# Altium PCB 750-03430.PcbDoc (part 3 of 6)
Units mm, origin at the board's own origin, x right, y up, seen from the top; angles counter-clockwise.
Board outline 141.61 x 63.5 mm, 6 copper layers (Top Layer, L2, L3, L4, L5, Bottom Layer), stack 1.557 mm thick; 401 components, 285 nets, 1356 pads, 1712 vias.
Unrouted connection lines stored in the file: 45.
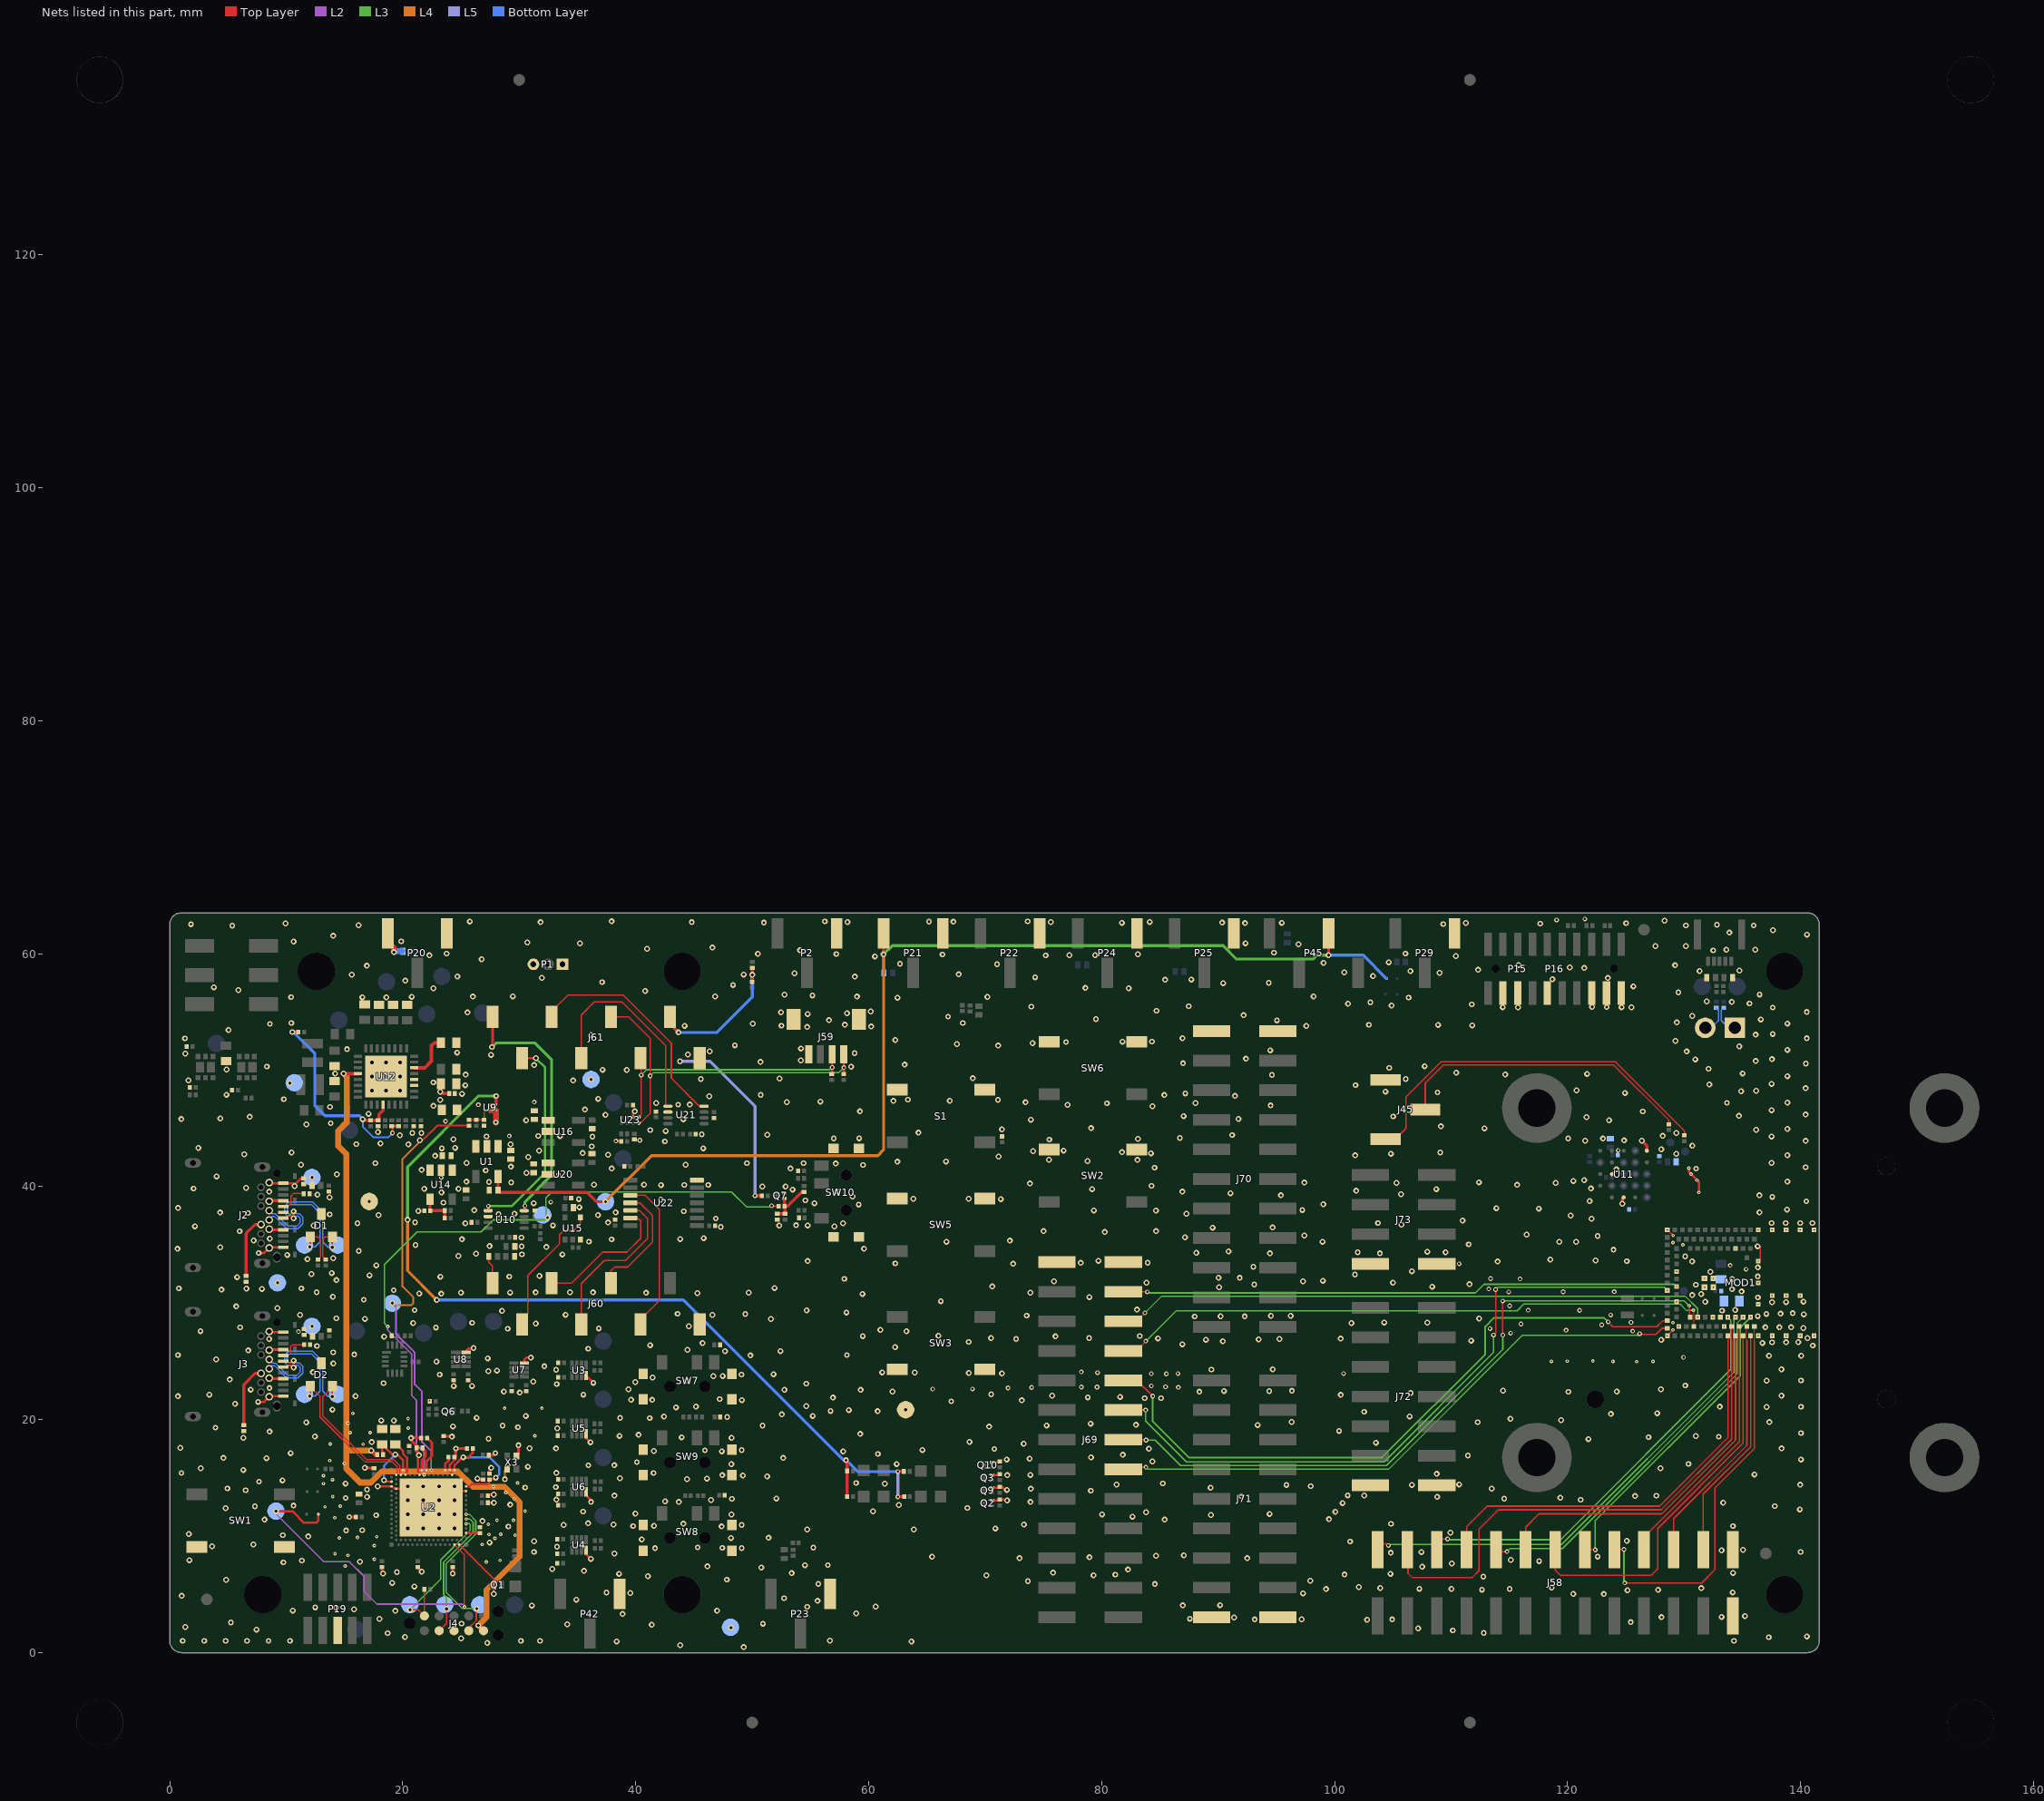
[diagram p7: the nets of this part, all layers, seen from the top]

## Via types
v1: diameter 0.5, hole 0.25, Top Layer to Bottom Layer, tented both sides, 1306 vias
v2: diameter 0.4, hole 0.2, Top Layer to Bottom Layer, tented both sides, 223 vias
v3: diameter 0.3, hole 0.1, Top Layer to L3, tented top, 74 vias
v4: diameter 0.3, hole 0.1, Top Layer to L3, tented both sides, 43 vias
v5: diameter 0.3, hole 0.1, Top Layer to L2, tented both sides, 31 vias
v6: diameter 0.61, hole 0.305, Top Layer to Bottom Layer, tented both sides, 25 vias
v7: diameter 0.3, hole 0.1, Top Layer to L2, tented top, 10 vias

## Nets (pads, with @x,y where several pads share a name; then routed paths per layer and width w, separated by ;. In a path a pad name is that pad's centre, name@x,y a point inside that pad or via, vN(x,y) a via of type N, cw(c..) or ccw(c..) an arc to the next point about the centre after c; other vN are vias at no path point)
1V8_LDO: C74.2 P21.3 P45.2 R34.1 SB5.2 TP5.1 U1.5 | length 103.6
  Top Layer w0.254: U1.5@28.186,40.873 28.186,39.698 C74.2@28.184,39.697 28.383,39.498 35.84,39.498 36.626,38.712 v1(37.411,38.712) ; v1(61.283,59.936) P21.3@61.283,61.755 ; P45.2@99.482,61.755 v1(99.482,59.866) 99.482,59.861 v1@99.492,59.852
  L3 w0.254: v1(61.283,59.936) 62.033,60.686 90.43,60.686 91.582,59.535 98.149,59.535 98.481,59.866 v1(99.482,59.866)
  L4 w0.254: v1(37.411,38.712) 41.357,42.657 60.788,42.657 61.283,43.152 v1(61.283,59.936)
  Bottom Layer w0.254: v1(61.283,59.936) 61.304,59.915 R34.1@61.304,58.35 ; v1@99.477,59.866 v1(99.482,59.866) 102.462,59.866 SB5.2@104.465,57.863
5V0: C4.1 C58.2 C61.2 C67.2 C73.2 C77.2 C79.2 C84.2 J4.5 J61.7 P20.3 R11.1 R36.1 R51.1 R88.2 R105.2 U1.1 U1.3 U9.A2 U9.B2 U12.4 U12.20 U14.1 U14.3 U16.1 U20.1 | length 101.6
  Top Layer w0.254: v1(23.224,48.15) 23.382,47.992 C77.2@23.9,47.992 ; J61.7@42.956,54.59 42.956,53.958 v1(43.679,53.235) ; R105.2@49.988,57.592 49.988,58.157 v1(50.017,58.186) 50.017,58.769 R88.2@50.009,58.769 ; v2(50.243,39.227) 50.848,39.227 R36.1@50.85,39.226
  Top Layer w0.3: v1(14.924,49.7) U12.4@16.174,49.7
  Top Layer w0.381: v1(17.298,17.348) 17.647,16.999 R11.1@17.786,16.999
  Top Layer w0.508: P20.3@18.714,61.755 18.714,61.041 19.257,60.498 v1(19.257,60.132) ; v1(26.499,2.342) 26.943,1.898 J4.5@26.943,1.884 ; U9.B2@27.51,46.545 U9.A2@28.01,46.545 28.01,45.534 v1(27.995,45.519)
  L4 w0.508: v1(14.924,49.7) 15.189,49.435 15.189,45.513 14.46,44.784 14.46,43.496 15.179,42.778 15.179,17.348 ; v1(17.298,17.348) 15.179,17.348 ; v1(26.499,2.342) 27.199,3.042 27.199,5.397 30.041,8.239 30.041,12.875 ; 30.041,12.925 28.72,14.246 26.038,14.246 24.724,15.56 18.222,15.56 17.267,14.605 16.347,14.605 15.179,15.774 15.179,17.348
  L5 w0.254: v1(43.805,50.765) 46.377,50.765 50.243,46.899 v2(50.243,39.227)
  Bottom Layer w0.254: v1(43.679,53.235) 46.976,53.235 50.019,56.278 50.019,58.184 v1(50.017,58.186)
  Bottom Layer w0.508: v1(19.257,60.132) 19.335,60.209 R51.1@19.933,60.209
  other v1: 30.774,42.536 24.498,43.334 29.259,43.634 30.597,45.691 23.224,47.45 22.624,48.95 14.199,49.7
5V0_LED: R20.2 R21.2 R68.2 R69.2 U9.A1 U9.B1 | length 75.9
  Top Layer w0.254: U9.B1@27.51,47.045 U9.A1@28.01,47.045 28.01,47.763 v1(28.029,47.782) ; v1(58.057,16.517) 58.151,16.423 R21.2@58.151,15.597 R68.2@58.151,13.403 ; v2(62.504,15.542) 62.526,15.564 R69.2@63.022,15.564 R69.2@63.041,15.546 ; v2(62.506,13.374) 62.535,13.403 R20.2@63.041,13.403
  L3 w0.254: v1(20.413,37.161) 20.413,41.697 26.497,47.782 v1(28.029,47.782)
  L4 w0.254: v1(20.413,37.161) 20.413,32.788 v1(22.926,30.275)
  L5 w0.254: v2(62.504,15.542) 62.506,15.54 v2(62.506,13.374)
  Bottom Layer w0.254: v1(22.926,30.275) 44.079,30.275 57.838,16.517 v1(58.057,16.517) 59.032,15.542 v2(62.504,15.542)
D_N: D1.3 J2.A7 J2.B7 R43.2 TP15.1 | length 18
  Top Layer w0.119: J2.A7@9.755,37.328 10.055,37.328 10.194,37.467 10.444,37.467 v1@10.635,37.276 ; R43.2@13.388,33.737 13.148,33.976 13.148,35.479 13.361,35.691 D1.3@13.974,35.691 13.974,35.613 13.974,34.812 v1(13.959,34.797)
  Bottom Layer w0.119: J2.B7@8.545,37.978 8.545,37.918 8.787,37.675 9.078,37.675 10.142,36.612 10.901,36.612 11.205,36.916 11.205,37.291 11.025,37.471 10.874,37.471 10.679,37.276 10.635,37.276 10.44,37.471 10.129,37.471 9.878,37.721 9.878,38.346 10.217,38.685 12.252,38.685 13.135,37.803 13.135,35.264 13.602,34.797 v1(13.959,34.797)
  other v1: 10.635,37.281
D_P: D1.2 J2.A6 J2.B6 R44.2 TP18.1 | length 17.7
  Top Layer w0.119: J2.A6@9.755,37.827 10.062,37.827 10.202,37.688 10.437,37.688 v1@10.635,37.886 ; v1(12.018,34.827) 12.074,34.883 D1.2@12.074,35.691 12.716,35.691 12.927,35.481 12.927,33.934 R44.2@12.73,33.737
  Bottom Layer w0.119: J2.B6@8.545,37.177 8.545,37.212 8.787,37.454 8.987,37.454 10.05,36.391 10.993,36.391 11.426,36.824 11.426,37.382 11.117,37.692 10.874,37.692 10.679,37.886 10.635,37.886 10.44,37.692 10.22,37.692 10.099,37.813 10.099,38.255 10.309,38.464 12.16,38.464 12.914,37.711 12.914,35.264 12.477,34.827 v1(12.018,34.827)
  other v1: 10.635,37.881
DBGR_BUTTON: SB2.2 TP62.1 U2.AL27 | length 30.9
  Top Layer w0.125: U2.AL27@24.445,9.25 25.301,8.394 v5(25.301,3.924)
  Top Layer w0.15: U2.AL27@24.445,9.232 U2.AL27@24.445,9.25
  Top Layer w0.2: v1(9.135,12.142) 10.535,12.142 11.527,11.151 12.59,11.151 12.763,11.324 SB2.2@12.763,11.889
  L2 w0.125: v1(9.135,12.142) 9.135,11.917 13.254,7.798 15.438,7.798 16.683,6.553 16.683,5.283 17.798,4.168 25.142,4.168 25.301,4.009 v5(25.301,3.924)
  Bottom Layer w0.125: TP62.1@9.126,12.15 v1(9.135,12.142)
DBGR_LED: Q1.1 U2.AL29 | length 4.5
  Top Layer w0.125: U2.AL29@24.845,9.25 24.898,9.25 27.814,6.334 Q1.1@27.814,6.05
DBGR_N: D2.3 J3.A7 J3.B7 TP16.1 U2.B4 | length 27.3
  Top Layer w0.119: J3.A7@9.755,24.518 10.055,24.518 10.194,24.658 10.444,24.658 v1@10.635,24.466 ; v1(13.959,21.988) 13.974,22.002 D2.3@13.974,22.804 ; D2.3@13.974,22.882 D2.3@13.974,22.804 ; U2.B4@19.845,15.274 19.755,15.364 19.755,16.042 19.217,16.581 16.872,16.581 13.131,20.323 13.131,21.961 D2.3@13.974,22.804
  Bottom Layer w0.119: J3.B7@8.545,25.168 8.545,25.108 8.787,24.866 9.078,24.866 10.142,23.803 10.901,23.803 11.205,24.107 11.205,24.481 11.025,24.661 10.874,24.661 10.679,24.466 10.635,24.466 10.44,24.661 10.129,24.661 9.86,24.93 9.86,25.519 10.217,25.876 12.252,25.876 13.135,24.993 13.135,22.455 13.602,21.988 v1(13.959,21.988)
  other v1: 10.635,24.472
DBGR_P: D2.2 J3.A6 J3.B6 TP17.1 U2.B2 | length 27.1
  Top Layer w0.119: J3.A6@9.755,25.018 10.062,25.018 10.202,24.879 10.437,24.879 v1@10.635,25.077 ; v1(12.018,22.018) 12.074,22.073 D2.2@12.074,22.882 12.074,22.829 12.91,21.993 12.91,20.231 16.781,16.36 19.126,16.36 19.535,15.951 19.535,15.364 U2.B2@19.445,15.274
  Bottom Layer w0.119: J3.B6@8.545,24.368 8.545,24.403 8.787,24.645 8.987,24.645 10.05,23.582 10.992,23.582 11.426,24.015 11.426,24.573 11.117,24.882 10.874,24.882 10.679,25.077 10.635,25.077 10.44,24.882 10.22,24.882 10.081,25.022 10.081,25.427 10.309,25.655 12.16,25.655 12.914,24.902 12.914,22.455 12.477,22.018 v1(12.018,22.018)
  other v1: 10.635,25.072
DBGR_RESET: J4.10 R6.1 TP3.1 U2.AC31 | length 13.6
  Top Layer w0.125: v1(20.631,3.683) 21.334,3.683 J4.10@21.863,3.154 21.863,5.431 R6.1@21.87,5.438
  L3 w0.125: v1(20.631,3.683) 23.261,6.314 23.261,7.976 25.805,10.52 25.805,10.983 25.713,11.074 v4(25.445,11.074)
DBGR_SWDCLK: J4.4 TP4.1 U2.W31 | length 13.7
  Top Layer w0.127: J4.4@25.673,1.884 25.673,2.13 26.316,2.773 26.316,3.728 v1(26.358,3.77)
  L3 w0.125: v4(25.445,11.874) 25.729,11.874 26.278,11.325 26.278,10.194 23.744,7.66 23.744,5.156 25.086,3.814 v1@26.428,3.814
DBGR_SWDIO: J4.2 TP2.1 U2.AA31 | length 11.4
  Top Layer w0.125: J4.2@23.133,1.884 23.766,2.517 v1(23.766,3.755)
  L3 w0.125: v1(23.766,3.755) 23.766,4.728 23.515,4.978 23.515,7.772 26.044,10.301 26.044,11.206 25.776,11.474 v4(25.445,11.474)
GND: C1.2 C2.1 C3.1 C4.2 C5.2 C6.2 C8.2 C9.2 C10.2 C11.2 C13.2 C18.2 C20.2 C21.1 C23.1 C24.1 C25.1 C26.1 C27.1 C28.1 C29.1 C30.1 C31.2 C32.2 C33.2 C34.2 C35.2 C36.2 C37.2 C38.1 C39.2 C40.2 C41.2 C42.2 C43.2 C44.2 C45.2 C46.1 C47.1 C48.1 C49.1 C50.1 C51.1 C52.2 C53.2 C54.1 C55.1 C56.1 C57.1 C58.1 C59.1 C60.1 C62.2 C63.2 C64.2 C65.2 C66.2 C68.2 C71.2 C72.1 C73.1 C74.1 C75.2 C76.2 C77.1 C79.1 C80.1 C84.1 C85.1 C87.2 C88.1 C89.1 C90.2 C96.1 C98.1 C99.1 D1.1 D2.1 J2.A1 J2.A12 J2.B1 J2.B12 J3.A1 J3.A12 J3.B1 J3.B12 J4.3 J45.1 J58.1 J58.2 J59.1 J59.5 J59.6 J60.8 J61.8 J69.1 J69.2 J70.1 J70.2 J71.17 J71.18 J72.13 J72.14 J73.7 J73.8 MOD1.1 MOD1.14 MOD1.18 MOD1.31 MOD1.33 MOD1.40 MOD1.48 MOD1.57 MOD1.80 MOD1.89 MOD1.90 MOD1.91 MOD1.92 MOD1.93 MOD1.94 MOD1.95 MOD1.96 MOD1.97 MOD1.98 MOD1.99 MOD1.100 MOD1.101 MOD1.102 MOD1.103 MOD1.G1 MOD1.G2 MOD1.G3 MOD1.G4 P1.3 P2.1 P15.3 P15.5 P15.9 P16.3 P16.5 P16.9 P16.15 P16.17 P16.19 P19.5 P20.1 P21.1 P22.1 P23.1 P24.1 P25.1 P29.1 P42.1 Q1.2 Q2.2 Q3.2 Q6.2 Q7.2 Q9.2 Q10.2 R2.2 R7.2 R8.2 R9.2 R12.2 R13.2 R14.2 R27.2 R29.2 R32.2 R38.2 R42.2 R45.1 R46.1 R47.2 R48.1 R49.1 R71.2 R72.2 R73.2 R74.2 R79.2 R80.2 R91.2 R92.2 R93.2 R94.2 R108.2 R116.1 R119.2 S1.1 S1.2 SW1.1 SW1.2 SW2.1 SW2.2 SW3.1 SW3.2 SW5.1 SW5.2 SW6.1 SW6.2 SW7.4 SW7.5 SW7.6 SW7.7 SW8.4 SW8.5 SW8.6 SW8.7 SW9.4 SW9.5 SW9.6 SW9.7 SW10.4 SW10.5 SW10.6 SW10.7 TP14.1 TP35.1 TP36.1 TP37.1 TP38.1 TP39.1 U1.2 U2.104 U2.A25 U2.B12 U2.B26 U2.G1 U2.H2 U2.J31 U3.4 U4.4 U5.4 U6.4 U7.4 U8.4 U9.C1 U10.2 U11.B3 U11.C1 U11.E5 U12.33 U14.2 U15.3 U16.2 U20.2 U21.2 U22.7 U23.B1 X3.2 X3.4 | length 50.2
  Top Layer w0.127: J70.2@95.131,53.361 95.397,53.361 J70.2@95.249,53.509 ; v3(128.559,27.2) 128.559,27.225 v5(129.041,27.707) ; v5(128.559,36.3) 129.05,35.809 v5(129.06,35.809) ; v1(136.314,34.885) 136.5,34.885 136.532,34.852 136.532,33.773 v3(136.359,33.6)
  Top Layer w0.2: v1(7.592,21.526) 8.102,21.526 J3.B1@8.545,21.968 8.595,22.018 J3.A12@9.755,22.018 ; v1(7.634,34.306) 8.104,34.306 J2.B1@8.545,34.747 8.595,34.797 J2.A12@9.755,34.797 ; J3.B12@8.545,27.568 8.595,27.518 J3.A1@9.755,27.518 ; J2.B12@8.545,40.347 8.595,40.298 J2.A1@9.755,40.298 10.857,40.298 11.285,40.726 C88.1@11.499,40.726 ; v1(17.852,14.274) U2.G1@19.045,14.274 19.096,14.274 19.296,14.074 U2.H2@19.445,14.074 20.245,14.074 v6(20.445,14.274) ; v1(21.395,16.949) 21.331,16.885 21.331,15.519 21.445,15.405 U2.B12@21.445,15.274 ; U2.B26@24.245,15.274 24.245,15.374 24.045,15.574 U2.A25@24.045,15.674 24.045,16.124 24.12,16.199 24.12,16.202 24.549,16.631 C44.2@24.549,16.774 ; v6(24.445,14.274) 24.845,13.874 U2.J31@25.445,13.874 ; U8.4@25.445,25.771 25.445,25.918 25.62,26.092 26.018,26.092 v1(26.084,26.158) ; U7.4@30.445,24.864 30.445,25.148 30.633,25.336 v1(30.999,25.336) ; U4.4@35.745,8.796 35.745,8.459 v1(36.145,8.059) ; U6.4@35.745,13.796 35.745,13.506 36.168,13.083 v1(36.168,12.936) ; U5.4@35.745,18.796 35.745,18.425 36.107,18.062 v1(36.128,18.062) ; U3.4@35.745,23.796 35.745,23.785 v1(36.369,23.161) ; v2(38.307,43.913) 38.323,43.898 R94.2@38.769,43.898 ; U23.B1@39.773,45.968 39.773,46.305 v1(39.93,46.462) ; Q2.2@70.586,13.061 71.175,13.061 R71.2@71.26,13.146 71.806,13.146 v1(71.884,13.068) ; Q9.2@70.586,14.152 71.175,14.152 R73.2@71.26,14.236 71.435,14.236 71.694,13.978 v1(71.873,13.978) ; Q3.2@70.586,15.242 71.175,15.242 R72.2@71.26,15.327 ; Q10.2@70.586,16.333 71.175,16.333 R74.2@71.26,16.418
  Top Layer w0.203: v1(20.72,18.424) 20.725,18.429 C39.2@21.495,18.429 ; v1(24.57,17.524) C32.2@25.52,17.524 ; R7.2@27.33,13.474 27.432,13.576 v1(27.821,13.576) ; C35.2@27.338,12.866 v1(27.829,12.866) ; Q1.2@27.814,5.6 27.814,5.044 v1(27.815,5.043) ; v3(130.408,41.592) 130.408,41.269 v3(130.605,41.073) 131.108,40.569 v3(131.108,40.557) 131.273,40.393 v3(131.273,39.506)
  Top Layer w0.225: U2.104@21.045,13.874 U2.104@22.445,12.474 U2.104@22.74,12.474 ; C31.2@23.52,18.574 24.147,18.574 v1@24.176,18.546 ; v1(26.42,14.949) v1@26.53,14.839 ; C33.2@27.445,15.409 27.445,15.799 v1@27.52,15.874
  Top Layer w0.25: v1(15.419,11.643) 15.429,11.653 C18.2@15.964,11.653 ; v1@16.745,15.799 16.805,15.859 C13.2@17.545,15.859 ; 20.945,18.023 21.164,17.805 21.164,17.304 21.395,17.073 v1(21.395,16.949) ; C44.2@24.545,16.774 v1@24.545,17.524 ; v1@26.53,14.839 C36.2@26.895,14.839 ; C37.2@27.426,16.963 27.782,16.963 v1(27.955,17.136)
  Top Layer w0.254: C20.2@18.219,7.314 18.219,6.976 v1@18.395,6.799 ; v1(20.72,18.424) 20.72,18.248 20.945,18.023 ; C53.2@21.297,7.314 21.297,7.299 v1(21.636,6.96) ; v1(24.295,6.799) C34.2@24.295,7.314 ; v1@28.773,14.862 28.773,15.582 X3.4@28.795,15.604 ; v1(29.941,17.808) 29.941,17.058 X3.2@29.945,17.054 ; U11.B3@123.8,41.077 v1@124.159,41.435 ; v1(124.701,38.534) 124.701,38.978 U11.C1@124.803,39.079 ; v1(126.369,43.941) 126.803,43.506 U11.E5@126.803,43.079
  other v1: 49.277,0.48 43.828,0.648 27.263,0.837 63.667,0.954 38.363,0.971 1.122,1.016 2.962,1.016 4.803,1.016 6.644,1.016 8.484,1.016 10.325,1.016 30.14,1.016 31.796,1.016 134.274,1.017 56.666,1.041 25.017,1.231 137.26,1.326 20.195,1.354 140.531,1.4 18.701,1.677 112.803,1.7 110.147,1.912 7.457,1.979 107.168,2.084 48.177,2.142 1.341,2.21 41.386,2.4 34.121,2.434 25.057,2.496 50.927,2.489 5.253,2.591 125.42,2.619 102.791,2.83 93.138,2.855 97.165,2.862 104.937,2.855 18.004,2.909 87.568,2.919 91.364,3.02 128.056,3.044 133.214,3.074 135.222,3.136 38.884,3.32 58.929,3.376 19.367,3.588 46.99,3.598 10.574,3.613 15.82,3.723 14.27,3.861 12.498,3.888 54.72,3.938 60.604,3.951 31.089,4.046 86.965,4.056 90.175,4.081 55.607,4.445 34.91,4.551 52.732,4.675 1.036,4.877 120.482,5.043 123.115,5.03 97.279,5.095 39.538,5.129 37.497,5.168 134.17,5.171 125.139,5.349 112.65,5.406 127.759,5.403 99.261,5.462 110.031,5.466 115.024,5.481 107.273,5.487 103.915,5.556 131.475,5.542 118.636,5.577 102.077,5.633 20.997,5.684 84.57,5.891 55.682,5.896 19.096,5.994 73.672,6.135 97.907,6.166 4.846,6.248 47.817,6.273 112.763,6.518 41.047,6.561 70.114,6.638 79.306,6.647 81.181,6.701 100.852,6.711 38.576,6.772 104.789,6.768 18.319,6.799 53.39,6.825 134.198,6.847 75.827,6.86 19.503,6.916 35.571,7.021 82.269,7.136 32.847,7.193 50.777,7.308 107.514,7.38 46.154,7.406 54.534,7.511 56.496,7.516 110.05,7.649 9.766,7.753 16.33,7.817 117.554,7.865 11.34,7.909 1.691,7.938 115.117,7.967 72.955,8.112 92.498,8.112 78.954,8.188 65.442,8.235 122.575,8.248 84.662,8.313 87.055,8.353 38.171,8.508 104.82,8.578 31.274,8.648 107.442,8.644 140.008,8.646 133.212,8.776 135.049,8.827 41.66,8.963 49.101,8.972 47.435,8.999 45.321,9.034 55.25,9.02 33.25,9.092 3.644,9.131 7.183,9.296 27.456,9.46 101.324,9.542 31.284,9.566 125.078,9.596 40.525,9.719 48.178,9.85 51.406,9.862 11.899,9.975 9.712,10.087 1.638,10.178 109.946,10.295 15.145,10.483 16.533,10.514 54.719,10.578 63.878,10.573 70.875,10.664 29.079,10.828 47.381,10.837 39.788,10.865 134.184,10.869 41.579,10.891 33.821,10.96 49.101,10.963 38.102,11.008 73.329,11.009 44.101,11.065 104.834,11.059 35.918,11.106 26.838,11.301 8.145,11.422 85.406,11.417 99.518,11.458 82.642,11.68 17.718,11.8 89.383,11.826 48.223,11.859 80.039,11.869 94.42,11.909 39.98,11.931 83.809,12.046 35.486,12.115 100.061,12.097 60.364,12.131 139.939,12.303 4.809,12.406 68.476,12.427 7.315,12.565 137.779,12.58 10.625,12.626 62.587,12.682 29.232,12.702 100.685,12.845 133.352,12.872 43.704,12.936 73.896,12.934 42.526,12.992 33.2,13.13 46.474,13.109 121.124,13.122 48.268,13.203 114.555,13.215 52.08,13.238 15.105,13.283 119.379,13.3 16.944,13.373 108.796,13.371 91.971,13.435 125.797,13.443 38.18,13.479 127.626,13.478 101.124,13.507 102.55,13.487 79.074,13.901 6.523,13.945 16.937,13.995 73.928,14.065 113.486,14.073 4.948,14.097 89.351,14.162 30.516,14.173 33.145,14.215 97.951,14.291 95.866,14.399 106.634,14.403 139.958,14.419 81.278,14.434 110.697,14.438 61.381,14.503 15.097,14.517 85.246,14.528 58.918,14.565 7.666,14.681 9.685,14.791 28.773,14.887 44.413,14.901 46.112,14.948 38.638,14.97 51.288,15.125 49.21,15.214 47.428,15.236 71.903,15.233 73.88,15.26 136.041,15.301 108.76,15.352 1.011,15.425 33.192,15.433 41.538,15.424 6.316,15.689 2.662,15.824 127.965,15.831 16.745,15.876 27.596,15.874 30.753,15.959 35.934,16.082 38.166,16.095 48.214,16.176 62.409,16.194 130.373,16.203 40.107,16.36 84.36,16.419 71.847,16.587 140.032,16.587 73.819,16.643 8.307,16.701 4.603,16.717 52.655,16.717 79.088,16.759 111.439,16.929 81.817,16.988 60.786,17.059 10.384,17.127 57.811,17.271 47.395,17.283 41.559,17.317 45.946,17.371 49.099,17.393 64.615,17.404 70.787,17.488 84.058,17.509 30.898,17.55 33.164,17.534 138.369,17.531 0.912,17.583 73.312,17.927 103.541,18.025 17.349,18.076 68.654,18.092 121.789,18.338 27.371,18.37 6.332,18.438 48.236,18.433 43.95,18.489 126.946,18.501 132.971,18.538 12.462,18.55 24.227,18.546 38.62,18.61 131.004,18.598 40.25,18.702 59.273,18.781 140.032,18.848 8.571,18.972 100.384,19.034 33.274,19.258 3.928,19.314 29.891,19.355 70.344,19.402 24.315,19.427 28.579,19.491 50.891,19.492 75.273,19.502 82.947,19.556 93.391,19.545 79.047,19.661 11.723,19.76 112.272,19.785 96.304,19.811 137.32,19.793 18.169,19.931 19.242,19.926 119.439,19.964 115.095,20.067 41.204,20.136 26.351,20.166 38.665,20.15 47.854,20.225 42.435,20.277 106.437,20.287 30.573,20.318 55.201,20.325 52.549,20.456 123.714,20.488 127.685,20.555 102.532,20.677 60.775,20.722 56.732,20.746 58.292,20.829 13.97,20.871 63.176,20.855 43.458,21.062 137.087,21.082 45.169,21.12 133.061,21.113 140.032,21.108 54.653,21.173 5.615,21.36 67.088,21.578 73.141,21.66 49.115,21.681 39.607,21.715 41.419,21.696 47.213,21.769 83.698,21.85 85.101,21.849 56.933,21.895 78.811,21.919 81.581,21.955 0.703,22.007 15.956,22.018 75.76,22.062 138.356,22.061 100.53,22.125 3.405,22.149 35.508,22.154 70.515,22.174 106.535,22.288 30.052,22.318 88.387,22.399 120.073,22.391 28.688,22.413 62.048,22.412 124.223,22.412 94.382,22.452 90.496,22.46 96.333,22.478 114.454,22.483 59.312,22.551 52.77,22.561 6.962,22.583 39.377,22.614 128.004,22.608 8.562,22.715 24.379,22.891 25.954,22.894 130.1,22.938 33.217,23.055 54.645,23.09 18.358,23.134 39.961,23.234 31.206,23.26 44.453,23.337 137.087,23.343 140.032,23.369 5.153,23.451 41.45,23.623 46.659,23.739 47.469,23.746 23.174,23.87 49.082,23.874 51.833,23.906 71.439,23.974 68.597,24.003 63.946,24.045 12.297,24.075 61.161,24.059 27.359,24.167 28.088,24.219 33.174,24.282 89.42,24.298 94.692,24.314 138.356,24.322 32.157,24.576 14.047,24.825 22.903,24.977 3.985,25.175 27.301,25.263 137.29,25.485 140.05,25.485 49.847,25.513 0.703,25.546 58.134,25.546 15.846,25.596 14.035,25.782 47.662,25.881 52.42,25.893 6.744,25.946 44.453,25.993 35.932,26.09 62.264,26.222 12.645,26.327 141.039,26.364 41.239,26.397 86.932,26.477 45.747,26.577 136.716,26.588 137.546,26.636 138.761,26.646 139.792,26.655 68.585,26.678 90.406,26.729 111.716,26.784 128.034,26.845 88.953,26.86 93.485,26.883 8.531,26.936 72.658,26.928 95.264,26.928 100.514,26.959 84.837,26.982 70.509,27.003 78.924,27.012 140.591,27.005 18.405,27.119 76.041,27.147 59.496,27.174 65.995,27.196 83.262,27.181 2.643,27.601 63.243,27.589 61.006,27.707 29.01,27.802 36.834,27.84 140.23,27.861 22.854,27.911 6.059,27.925 136.976,27.93 138.186,27.93 139.192,27.932 44.558,28.019 31.425,28.259 20.896,28.29 101.442,28.293 25.96,28.311 104.26,28.346 107.959,28.331 51.607,28.644 16.754,28.653 14.301,28.699 112.409,28.685 87.989,28.857 92.285,28.86 90.215,28.884 136.323,28.891 94.53,28.916 96.218,28.915 73.562,28.935 11.187,28.995 33.98,29.006 46.595,28.992 140.268,29.041 49.408,29.062 43.598,29.089 137.063,29.083 138.278,29.093 139.32,29.136 58.095,29.198 28.534,29.343 54.674,29.378 21.021,29.399 134.379,29.427 83.041,29.451 9.237,29.58 5.713,29.722 137.546,30.086 138.761,30.096 131.809,30.125 140.251,30.138 66.193,30.177 16.66,30.294 136.327,30.494 78.94,30.523 14.006,30.542 130.699,30.696 59.467,30.794 131.459,30.791 21.422,30.828 23.316,30.814 45.308,30.87 25.001,30.901 40.892,30.887 49.709,30.894 73.876,30.908 12.615,30.934 29.22,30.912 31.412,30.928 34.355,30.935 36.332,30.924 134.93,31.004 19.231,31.118 4.442,31.159 134.111,31.198 7.924,31.222 6.589,31.247 0.779,31.273 11.299,31.273 51.928,31.306 90.083,31.365 108.374,31.419 70.608,31.43 93.097,31.595 131.005,31.584 111.569,31.631 105.012,31.749 9.254,31.75 83.85,31.757 75.903,31.869 97.285,31.878 98.989,31.926 14.321,31.975 134.118,32.078 57.903,32.09 91.854,32.176 90.033,32.19 5.795,32.239 23.233,32.275 29.153,32.286 136.325,32.288 31.742,32.336 17.155,32.395 101.741,32.451 12.173,32.502 13.901,32.591 132.251,32.692 106.635,32.74 136.333,33.073 93.022,33.114 17.735,33.252 72.406,33.384 62.289,33.412 78.204,33.457 83.952,33.466 113.995,33.577 130.679,33.591 54.764,33.618 125.08,33.606 79.723,33.635 122.399,33.661 118.516,33.751 11.827,33.78 14.03,33.861 130.094,34.016 24.782,34.053 10.087,34.146 33.714,34.184 30.236,34.191 26.299,34.256 94.441,34.279 103.888,34.275 88.119,34.319 101.979,34.359 109.523,34.373 107.948,34.414 90.889,34.436 16.231,34.488 123.942,34.586 0.666,34.663 59.606,34.685 4.34,34.788 32.342,34.824 30.215,34.88 27.455,34.901 21.101,34.991 111.511,35.045 35.986,35.28 66.677,35.276 98.962,35.278 119.292,35.266 120.735,35.255 7.204,35.376 72.122,35.367 37.933,35.473 25.079,35.484 43.821,35.506 8.592,35.541 45.833,35.588 30.188,35.634 87.15,35.646 122.574,35.772 97.411,35.81 116.49,35.885 80.268,36.105 5.996,36.175 75.008,36.187 84.676,36.187 89.526,36.483 94.679,36.499 47.31,36.545 2.167,36.597 57.066,36.591 12.351,36.661 52.326,36.661 54.76,36.673 32.899,36.679 53.772,36.694 105.734,36.744 25.376,36.851 16.115,36.861 57.803,36.862 103.725,36.876 137.502,36.88 138.717,36.88 139.957,36.88 141.009,36.88 37.627,36.926 21.062,36.934 110.979,37.093 122.058,37.255 46.876,37.267 120.263,37.527 17.921,37.557 36.766,37.553 13.732,37.615 28.226,37.639 29.595,37.675 87.274,37.681 6.724,37.735 4.328,37.78 38.284,37.793 136.472,37.799 44.137,37.891 21.342,37.916 84.656,37.941 79.332,37.958 26.152,37.979 97.228,38.001 138.828,38.037 117.525,38.12 0.723,38.166 113.886,38.151 35.165,38.234 59.147,38.464 99.022,38.488 55.342,38.58 31.245,38.584 23.504,38.631 17.128,38.727 140.486,38.749 121.884,38.762 54.564,38.827 42.146,38.886 35.117,38.933 71.341,38.934 68.592,38.953 63.83,38.963 13.724,39.079 137.569,39.125 58.616,39.149 95.392,39.257 136.464,39.262 12.685,39.316 105.69,39.352 91.055,39.442 23.329,39.509 8.547,39.573 57.317,39.595 86.927,39.575 101.857,39.646 53.465,39.754 79.18,39.79 108.725,39.794 21.852,39.818 24.796,39.819 2.053,39.838 122.003,39.843 6.56,39.9 50.877,40.014 52.865,40.007 10.729,40.047 84.281,40.073 42.173,40.139 44.171,40.146 46.228,40.146 36.428,40.166 40.718,40.163 115.661,40.159 73.838,40.269 105.305,40.322 118.981,40.32 97.402,40.349 29.321,40.368 112.38,40.372 27.411,40.403 25.469,40.428 138.864,40.44 120.492,40.492 121.417,40.561 4.021,40.885 14.342,41.07 30.621,41.183 27.128,41.397 21.632,41.438 124.184,41.483 131.027,41.548 37.944,41.555 53.279,41.554 84.541,41.626 140.433,41.668 29.29,41.712 11.268,41.879 44.288,41.883 59.51,41.863 57.173,41.987 17.663,42.018 49.541,42.02 54.411,42.02 25.487,42.04 137.516,42.044 62.461,42.14 66.638,42.164 78.789,42.192 75.482,42.302 83.081,42.295 71.153,42.575 22.785,42.649 101.761,42.687 138.864,42.701 37.632,42.736 6.395,42.782 129.334,42.81 104.829,42.826 84.231,42.865 35.446,42.882 10.468,42.936 109.067,42.926 81.744,42.959 74.123,43.051 31.714,43.086 76.736,43.1 128.038,43.199 23.358,43.293 45.794,43.299 2.461,43.317 36.228,43.459 130.709,43.517 20.488,43.63 16.019,43.653 18.096,43.717 42.513,43.889 121.512,43.938 140.433,43.929 124.846,43.97 24.359,44.067 75.507,44.044 83.111,44.103 120.044,44.14 123.04,44.126 57.006,44.145 59.187,44.155 86.712,44.184 27.197,44.317 36.289,44.297 137.516,44.305 31.637,44.352 33.512,44.349 128.17,44.362 19.764,44.407 91.199,44.43 51.297,44.458 45.672,44.485 20.829,44.6 21.607,44.608 129.331,44.602 64.278,44.632 17.878,44.69 42.575,44.777 41.248,44.863 136.192,44.884 71.44,44.923 138.864,44.962 79.087,45.021 112.857,45.012 109.127,45.176 11.74,45.353 13.821,45.446 123.556,45.699 73.915,45.752 44.08,45.785 1.003,45.8 91.746,45.819 4.35,45.854 121.621,45.967 6.867,45.993 105.02,46.029 87.032,46.059 134.714,46.077 37.409,46.157 140.433,46.19 17.064,46.255 126.447,46.454 59.255,46.464 137.516,46.566 35.648,46.616 13.765,46.847 84.353,46.903 94.504,46.97 43.646,47.038 77.07,47.025 44.634,47.046 80.45,47.157 41.762,47.182 88.05,47.175 133.675,47.195 73.469,47.241 138.864,47.222 52.978,47.26 55.859,47.305 62.12,47.363 66.963,47.369 63.372,47.47 71.099,47.458 9.803,47.509 36.786,47.544 46.31,47.756 91.448,47.787 85.386,47.869 4.869,47.888 50.733,47.88 25.094,47.965 87.179,48.003 124.922,48.049 108.83,48.093 104.363,48.163 134.886,48.189 136.192,48.228 120.768,48.27 140.433,48.45 25.379,48.711 101.792,48.714 132.159,48.781 137.516,48.826 10.313,48.887 1.613,49.12 34.64,49.112 36.167,49.2 45.595,49.244 106.108,49.233 52.353,49.276 68.935,49.31 138.864,49.483 94.617,49.587 25.405,49.615 114.638,49.633 121.67,49.682 135.03,49.717 110.438,49.782 37.153,50.035 39.243,50.017 4.879,50.066 132.099,50.119 104.691,50.195 58.492,50.29 8.34,50.309 107.733,50.342 31.283,50.438 63.087,50.478 140.451,50.566 86.986,50.594 50.716,50.711 136.153,50.788 54.182,50.832 130.955,50.924 137.535,50.942 92.394,50.981 27.591,51.32 44.482,51.341 1.342,51.426 58.792,51.458 24.677,51.515 130.218,51.602 46.356,51.621 94.467,51.71 138.864,51.743 15.224,51.8 54.19,51.858 134.729,52.042 71.115,52.108 48.514,52.131 67.577,52.243 74.067,52.323 76.939,52.415 81.784,52.443 84.311,52.452 129.258,52.512 62.293,52.584 1.313,52.729 86.941,52.752 140.526,52.735 36.145,53.023 136.132,53.043 137.609,53.111 5.048,53.443 54.723,53.707 60.212,53.748 44.196,53.808 52.521,53.817 97.569,53.8 111.809,53.844 102.941,53.895 108.881,53.883 57.957,53.898 8.6,53.974 50.054,53.987 138.864,54.004 10.443,54.051 68.088,54.051 129.376,54.092 95.045,54.278 56.594,54.292 136.586,54.354 79.51,54.381 66.813,54.593 130.695,54.658 92.183,54.716 54.762,54.82 58.139,54.89 25.555,54.951 52.482,54.969 140.526,54.995 60.18,55.049 84.713,55.102 115.747,55.389 125.48,55.391 137.609,55.371 114.434,55.402 123.358,55.413 124.631,55.405 122.104,55.437 73.965,55.454 87.469,55.489 104.891,55.556 111.775,55.645 101.156,55.704 135.612,55.721 103.066,55.826 134.092,55.863 131.935,55.9 62.472,56.22 106.346,56.231 18.6,56.257 10.422,56.27 16.54,56.262 20.786,56.303 70.198,56.292 26.031,56.312 29.462,56.336 46.816,56.335 58.998,56.318 98.198,56.323 55.175,56.421 52.786,56.492 136.476,56.495 129.505,56.682 40.813,56.792 5.898,56.879 22.645,57.027 82.317,57.034 78.606,57.056 3.794,57.12 125.647,57.197 48.358,57.317 90.431,57.472 94.347,57.498 37.116,57.553 20.227,57.679 85.456,57.757 87.693,57.783 118.687,57.8 31.941,57.918 123.456,57.914 74.292,57.972 58.813,58.033 24.694,58.048 103.292,58.086 15.624,58.194 49.28,58.208 67.738,58.226 53.632,58.307 109.005,58.357 100.832,58.386 106.498,58.506 131.33,58.512 134.74,58.542 112.321,58.61 121.43,58.767 120.184,58.819 16.926,58.963 115.776,59.029 129.226,59.005 71.023,59.099 62.687,59.127 99.053,59.204 104.647,59.26 26.783,59.52 60.538,59.764 110.407,59.8 22.294,59.861 75.193,59.853 77.24,59.872 79.439,59.877 66.342,59.927 57.227,59.968 83.108,59.957 50.492,59.98 23.772,60.008 106.071,60.006 94.789,60.088 54.117,60.288 132.498,60.278 133.632,60.335 136.105,60.343 40.987,60.419 46.594,60.521 127.549,60.642 130.145,60.645 96.891,60.806 35.222,60.881 92.353,60.894 30.703,60.969 10.632,61.035 19.883,61.062 14.033,61.535 140.544,61.633 133.878,61.809 137.627,62.009 5.371,62.406 130.145,62.423 135.974,62.422 16.211,62.447 132.819,62.484 1.826,62.529 109.334,62.54 117.649,62.579 9.939,62.597 92.314,62.624 111.267,62.632 125.022,62.615 51.01,62.661 81.738,62.648 95.465,62.646 90.345,62.662 31.842,62.705 44.815,62.7 58.176,62.719 75.629,62.712 84.117,62.725 65.179,62.759 67.278,62.742 25.769,62.766 37.934,62.777 56.234,62.771 73.658,62.772 128.325,62.833
  other v2: 65.502,22.628 68.915,22.63 71.964,22.723 73.985,22.764 86.582,22.772 78.258,22.801 79.604,22.801 85.489,22.822 84.27,22.897 84.262,23.949 85.556,23.932 86.554,23.96 100.773,23.962 79.65,24.031 78.258,24.1 129.943,25.35 115.107,27.425 11.053,27.562 125.585,27.602 119.874,27.682 113.341,27.811 122.929,28.137 115.995,28.218 125.442,28.351 123.701,28.976 121.026,29.382 116.621,29.395 115.021,29.772 114.945,30.972 119.618,30.982 123.996,30.993 113.23,31.218 115.918,32.083 113.389,32.106 135.321,32.92 133.955,33.25 110.692,33.38 32.718,38.677 23.316,40.78 33.371,41.041 124.334,43.12 40.354,43.989 29.154,44.351 23.682,45.624 26.494,47.038 31.293,47.267 119.057,62.893 121.482,62.972
  other v3: 17.572,8.026 15.311,8.357 17.572,9.195 14.549,9.855 16.124,9.881 17.775,9.957 27.348,11.027 30.5,12.141 13.33,12.522 14.651,12.573 13.203,14.503 13.203,15.189 16.608,17.9 13.787,17.907 31.339,18.618 17.213,18.894 15.311,19.71 28.748,20.98 31.948,20.98 123.892,25.014 127.317,25.007 119.973,25.026 136.359,27.2 137.559,27.2 138.759,27.2 139.959,27.2 141.159,27.2 129.534,28 133.434,28 132.459,28.8 136.359,29.9 137.559,30.65 138.759,30.65 139.959,30.65 131.759,31.375 132.509,31.375 136.359,31.75 131.759,32.125 132.509,32.125 134.409,34.7 136.359,36.3 137.559,36.3 138.759,36.3 139.959,36.3 141.159,36.3
  other v4: 15.057,7.442 27.174,7.781 28.369,7.922 14.194,8.505 26.838,9.293 27.925,9.814 29.653,10.082 27.414,10.15 28.411,10.16 28.097,11.376 29.506,11.361 14.165,11.582 29.575,13.2 14.001,13.409 28.858,13.737 27.788,14.253 29.875,14.557 13.962,14.85 14.998,16.232 13.738,16.492 15.494,18.897 23.691,20.486 15.716,20.545 22.309,21.629
  other v5: 20.49,19.279 20.463,20.103 125.93,24.978 118.6,25.012 122.163,25.028 129.049,28.334 129.359,30.125 129.359,32.725 129.899,34.996 129.048,35.209
  other v6: 20.445,10.674 21.778,10.674 23.112,10.674 24.445,10.674 20.445,11.874 21.778,11.874 23.112,11.874 24.445,11.874 20.445,13.074 21.778,13.074 23.112,13.074 24.445,13.074 21.778,14.274 23.112,14.274 17.374,48.25 18.574,48.25 19.774,48.25 17.374,49.45 18.574,49.45 19.774,49.45 17.374,50.65 18.574,50.65 19.774,50.65
LDOS_FLASH_DIS: R85.1 TP60.1 U2.B14 | length 57.7
  Top Layer w0.127: v2(51.67,38.358) 51.714,38.314 R85.1@52.27,38.314
  L2 w0.127: v4(18.715,27.991) 18.715,27.686 20.772,25.629 20.772,22.088 21.179,21.681 21.179,17.882 21.229,17.832 21.229,17.803 21.845,17.187 v7(21.845,15.274)
  L3 w0.127: v4(18.715,27.991) 18.435,28.27 18.435,33.325 21.229,36.119 26.738,36.119 27.774,37.154 32.244,37.154 v1(32.441,37.352) 32.298,37.496 32.298,39.041 32.804,39.548 48.229,39.548 49.52,38.257 51.569,38.257 v2(51.67,38.358)
LDOS_FLASH_DISA: Q7.1 R85.2 R86.1 R113.2 R116.2 | length 4.2
  Top Layer w0.254: R116.2@52.162,37.688 52.164,37.685 R86.1@52.818,37.685 52.818,38.266 R85.2@52.77,38.314 ; Q7.1@52.772,39.001 52.772,38.316 R85.2@52.77,38.314 ; R113.2@54.447,39.558 54.26,39.558 53.016,38.314 R85.2@52.77,38.314
LED_PWR_CTRL: R84.1 TP82.1 U2.A17 | length 37.4
  Top Layer w0.152: v1(21.48,43.985) 21.721,43.985 22.969,45.233 R84.1@25.686,45.233
  L2 w0.152: v1(19.115,29.997) 19.426,29.686 19.426,27.356 21.03,25.752 21.03,23.029 21.661,22.397 21.661,18.085 22.445,17.301 v5(22.445,15.674)
  L4 w0.152: v1(19.115,29.997) 19.29,29.822 20.731,29.822 20.916,30.008 20.916,30.501 19.977,31.441 19.977,42.374 21.48,43.877 v1(21.48,43.985)
LED_PWR_CTRL1: R79.1 R84.2 R89.2 U9.C2 | length 2.1
  Top Layer w0.127: R84.2@25.686,45.733 26.314,45.733 R89.2@26.32,45.739 R79.1@26.98,45.738 ; R79.1@27.01,45.769 U9.C2@27.01,46.545
MikroE_AN: J60.1 R33.2 | length 2.4
  Top Layer w0.127: R33.2@27.398,34.022 27.398,33.518 27.716,33.201 J60.1@27.716,31.73
MikroE_INT: J61.2 U10.1 | length 17.7
  Top Layer w0.203: U10.1@27.36,37.965 v2(27.36,38.327) ; J61.2@30.256,51.034 31.431,51.034 v1(31.437,51.027)
  L3 w0.203: v2(27.36,38.327) 29.341,38.327 32.223,41.209 32.223,50.241 v1(31.437,51.027)
MikroE_PWM: J61.1 U10.8 | length 22.4
  Top Layer w0.203: U10.8@30.431,37.936 30.489,37.995 v2(30.489,38.356)
  Top Layer w0.254: v1(27.665,51.986) 27.716,52.037 J61.1@27.716,54.59
  L3 w0.254: v1(27.665,51.986) 28.012,52.333 31.371,52.333 32.777,50.927 32.777,40.988 30.489,38.7 v2(30.489,38.356)
MikroE_RESET: J60.2 U15.4 | length 11.8
  Top Layer w0.127: J60.2@30.256,28.174 30.256,28.635 30.74,29.118 30.74,32.37 33.455,35.086 33.455,35.873 33.795,36.213 34.661,36.213 35.259,36.81 U15.4@35.259,37.372
MikroE_SCL: J59.4 J61.5 R3.1 U23.A2 | length 30.5
  Top Layer w0.127: J61.5@37.876,54.59 39.379,54.59 41.245,52.724 v2(41.245,49.513) 41.245,46.301 40.411,45.468 U23.A2@40.273,45.468
  Top Layer w0.203: R3.1@57.865,49.651 57.865,50.22 v2(57.869,50.223) 57.865,50.226 J59.4@57.865,51.374
  L3 w0.127: v2(41.245,49.513) 41.504,49.772 57.418,49.772 v2(57.869,50.223)
MikroE_SDA: J59.3 J61.6 R10.1 U23.A1 | length 23.6
  Top Layer w0.127: U23.A1@40.273,45.968 40.473,46.169 v2(40.473,49.575) 40.473,50.976 J61.6@40.416,51.034
  Top Layer w0.203: R10.1@56.831,49.651 56.865,49.686 56.865,50.231 v2(56.868,50.233) 56.865,50.235 J59.3@56.865,51.374
  L3 w0.127: v2(40.473,49.575) 40.935,50.037 56.672,50.037 v2(56.868,50.233)
MikroE_SPI_CLK: J60.4 U22.12 | length 14.3
  Top Layer w0.127: J60.4@35.336,28.174 35.336,31.683 37.325,33.672 39.137,33.672 41.017,35.552 41.017,37.27 40.325,37.961 U22.12@39.554,37.961
MikroE_SPI_CS: J60.3 U22.13 | length 11.7
  Top Layer w0.127: J60.3@32.796,31.73 34.502,31.73 37.163,34.39 39.249,34.39 40.426,35.566 40.426,37.044 40.159,37.311 U22.13@39.554,37.311
MikroE_SPI_MISO: J60.5 U22.11 | length 10.3
  Top Layer w0.127: J60.5@37.876,31.73 37.876,32.774 38.202,33.1 39.297,33.1 41.439,35.241 41.439,37.534 40.361,38.611 U22.11@39.554,38.611
MikroE_SPI_MOSI: J60.6 U22.10 | length 13.5
  Top Layer w0.127: U22.10@39.554,39.261 40.8,39.261 42.045,38.016 42.045,30.242 40.416,28.613 J60.6@40.416,28.174
MikroE_UART_RX: J61.3 U21.8 | length 19.8
  Top Layer w0.127: J61.3@32.796,54.59 32.796,55.058 34.17,56.432 38.955,56.432 43.059,52.327 43.059,49.312 45.466,46.905 U21.8@45.871,46.905
MikroE_UART_TX: J61.4 U21.1 | length 18.3
  Top Layer w0.127: J61.4@35.336,51.034 35.336,54.74 36.47,55.874 38.798,55.874 42.566,52.106 42.566,46.983 42.643,46.905 U21.1@42.771,46.905
NetC1_1: C1.1 U2.AG31 | length 1.2
  Top Layer w0.203: U2.AG31@25.445,10.274 26.614,10.274 C1.1@26.63,10.259
NetC5_1: C5.1 P1.1 U12.19
  other v1: 22.636,46.933
NetC7_2: C7.2 R90.2 R91.1 U14.4 | length 2.9
  Top Layer w0.254: U14.4@22.349,38.918 22.349,37.952 R90.2@23.626,37.952 23.622,37.948 C7.2@23.622,37.305
NetC29_2: C29.2 MOD1.15 R1.2
  other v1: 133.253,29.362
NetC32_1: C32.1 C33.1 U2.A27 U2.G31 | length 9.8
  Top Layer w0.2: U2.A27@24.445,15.674 24.445,16.067 v1@25.152,16.774 ; v1(25.195,16.774) 25.657,16.774 26.006,17.124 26.006,17.511 C32.1@26.02,17.524 ; U2.G31@25.445,14.274 25.745,14.274 25.945,14.474 27.287,14.474 27.445,14.633 C33.1@27.445,14.875 ; C33.1@27.56,14.889 27.785,14.889
  Bottom Layer w0.2: v1(25.195,16.774) 27.442,16.774 28.291,15.926 28.291,15.32 v1(27.995,15.024)
NetC38_2: C38.2 U12.22 | length 3.9
  Top Layer w0.305: U12.22@20.974,50.201 21.901,50.201 22.467,50.766 22.467,52.097 22.72,52.351 C38.2@23.224,52.351
NetC39_1: C39.1 U2.A15 | length 3.1
  Top Layer w0.225: U2.A15@22.045,15.674 22.045,16.411 22.495,16.861 22.495,18.027 C39.1@22.092,18.429
NetC42_1: C42.1 R11.2 U2.A5 U2.E1 | length 7.5
  Top Layer w0.158: v1(18.395,14.799) 18.52,14.674 U2.E1@19.045,14.674
  Top Layer w0.2: C42.1@18.245,17.854 18.245,17.249 18.355,17.139 R11.2@18.355,16.999 ; C42.1@18.395,17.704 18.545,17.854 18.545,17.574 19.108,17.011 v1(19.373,17.011) 19.533,17.011 20.045,16.499 U2.A5@20.045,15.674
  Bottom Layer w0.2: v1(18.395,14.799) 18.395,16.034 v1(19.373,17.011)
NetC43_1: C43.1 U2.B6 | length 3.1
  Top Layer w0.187: C43.1@19.37,17.854 19.49,17.854 20.02,17.324 20.02,17.074 20.376,16.718 20.376,15.548 ; U2.B6@20.245,15.274 20.376,15.544
NetC44_1: C44.1 U2.A23 | length 1.2
  Top Layer w0.2: U2.A23@23.645,15.674 23.645,16.186 23.979,16.52 C44.1@23.979,16.774
NetC45_1: C45.1 U2.A13 | length 2.1
  Top Layer w0.225: U2.A13@21.645,15.674 21.645,16.519 21.945,16.819 21.945,17.329 C45.1@21.695,17.579
NetC71_1: C71.1 R103.2 R104.2 R106.2 R107.1 U12.12 | length 20.1
  Top Layer w0.15: R106.2@19.061,45.199 R106.2@19.062,45.197 ; v2(19.123,44.611) 19.123,45.136 R106.2@19.062,45.197 ; R107.1@19.642,45.197 R106.2@19.062,45.197
  Top Layer w0.254: v1(10.522,53.27) 10.53,53.262 R104.2@11.064,53.262 ; v1(16.571,45.786) 16.571,45.763 16.634,45.7 17.254,45.7 17.974,45.7 17.974,46.21 18.324,46.56 U12.12@18.324,47.05
  Bottom Layer w0.15: v1(16.571,45.786) 16.571,45.152 17.494,44.228 18.74,44.228 v2(19.123,44.611)
  Bottom Layer w0.254: v1@10.604,53.271 12.46,51.415 12.46,46.946 13.327,46.078 16.306,46.078 16.571,45.813 v1(16.571,45.786)
NetC88_2: C88.2 FB1.1 J2.A4 J2.A9 J2.B4 J2.B9 TP12.1 | length 2.5
  Top Layer w0.254: J2.B4@8.545,36.347 8.595,36.298 J2.A9@9.755,36.298 ; J2.B9@8.545,38.747 8.595,38.797 J2.A4@9.755,38.797
  other v1: 12.213,40.793
NetC89_2: C89.2 FB2.1 J3.A4 J3.A9 J3.B4 J3.B9 TP13.1 | length 2.5
  Top Layer w0.254: J3.B4@8.545,23.568 8.595,23.518 J3.A9@9.755,23.518 ; J3.B9@8.545,25.968 8.595,26.018 J3.A4@9.755,26.018
  other v1: 12.213,28.013
NetJ1_1: J1.1 R70.2 | length 2.5
  Bottom Layer w0.127: R70.2@133.321,55.246 133.194,55.12 133.194,54.907 133.194,54.266 133.825,53.635 J1.1@134.386,53.635
NetJ1_2: J1.2 R4.2 | length 2.6
  Bottom Layer w0.127: J1.2@131.813,53.635 132.334,53.635 132.94,54.241 132.94,55.109 132.754,55.295 R4.2@132.754,55.356
NetJ2_A5: J2.A5 R49.2 | length 2.6
  Top Layer w0.119: J2.A5@9.755,38.298 10.14,38.298 10.407,38.565 10.407,39.19 10.637,39.419 11.489,39.419 R49.2@11.519,39.39
NetJ2_B5: J2.B5 R45.2 | length 5.2
  Top Layer w0.25: R45.2@6.56,32.342 6.56,35.993 7.314,36.747 J2.B5@7.845,36.747
NetJ3_A5: J3.A5 R47.1 | length 2.5
  Top Layer w0.119: J3.A5@9.68,25.518 10.13,25.518 10.384,25.772 10.384,26.304 10.516,26.436 R47.1@11.531,26.436
NetJ3_B5: J3.B5 R46.2 | length 5.4
  Top Layer w0.25: R46.2@6.357,19.53 6.357,23.011 7.314,23.968 J3.B5@7.845,23.968
NetJ45_2: J45.2 R96.1 | length 26.1
  Top Layer w0.124: J45.2@107.778,46.624 107.778,48.889 109.344,50.454 123.946,50.454 128.689,45.711 R96.1@128.689,45.363
NetJ45_3: J45.3 R95.1 | length 32.8
  Top Layer w0.124: J45.3@104.378,44.084 105.216,44.084 106.126,44.993 106.126,47.697 109.165,50.736 124.076,50.736 130.026,44.785 R95.1@130.026,44.408
NetJ58_3: J58.3 MOD1.4 | length 20
  Top Layer w0.102: 135.709,26.75 MOD1.4@135.709,27.2
  Top Layer w0.127: J58.3@131.638,8.856 131.638,13.604 135.709,17.675 135.709,26.75
NetJ58_5: J58.5 MOD1.5 | length 21.7
  Top Layer w0.076: 135.384,26.75 MOD1.5@135.384,28
  Top Layer w0.127: J58.5@129.098,8.856 129.098,11.504 135.384,17.791 135.384,26.75
NetJ58_7: J58.7 MOD1.8 | length 22.5
  Top Layer w0.076: 134.734,26.75 MOD1.8@134.734,28
  Top Layer w0.127: J58.7@126.558,8.856 126.558,9.928 134.734,18.104 134.734,26.75
NetJ58_9: J58.9 MOD1.2 | length 34.2
  Top Layer w0.076: 136.034,26.75 MOD1.2@136.034,28
  Top Layer w0.127: J58.9@124.018,8.856 124.829,8.856 v2(124.834,8.861) ; v2(124.908,5.989) 131.513,5.989 132.653,7.13 132.653,14.14 136.034,17.521 136.034,26.75
  L3 w0.127: v2(124.834,8.861) 124.834,6.063 v2(124.908,5.989)
NetJ58_11: J58.11 MOD1.3 | length 26.4
  Top Layer w0.127: J58.11@121.478,8.856 122.337,8.856 v2(122.374,8.819)
  L3 w0.127: v2(122.374,8.819) 122.374,11.338 134.815,23.779 134.815,27 134.815,27.906 v3(135.709,28.8)
NetJ58_13: J58.13 MOD1.7 | length 34
  Top Layer w0.102: 135.059,26.75 MOD1.7@135.059,27.2
  Top Layer w0.127: J58.13@118.938,8.856 118.938,7.092 119.378,6.652 127.173,6.652 127.727,7.206 127.727,10.658 135.059,17.99 135.059,26.75
NetJ58_15: J58.15 MOD1.10 | length 32
  Top Layer w0.102: 134.409,26.75 MOD1.10@134.409,27.2
  Top Layer w0.127: J58.15@116.398,8.856 116.398,10.771 117.543,11.916 128.086,11.916 134.409,18.239 134.409,26.75
NetJ58_17: J58.17 MOD1.6 | length 32.2
  Top Layer w0.127: J58.17@113.858,8.856 114.036,8.677 v2(114.795,8.677)
  L3 w0.124: v2(114.795,8.677) 115.059,8.941 119.562,8.941 134.539,23.918 134.539,27 134.539,28.28 v3(135.059,28.8)
NetJ58_19: J58.19 MOD1.13 | length 36.3
  Top Layer w0.102: 133.759,26.75 MOD1.13@133.759,27.2
  Top Layer w0.127: J58.19@111.318,8.856 111.341,8.879 111.341,10.829 113.097,12.585 127.884,12.585 133.759,18.46 133.759,26.75
NetJ58_21: J58.21 MOD1.12 | length 36.7
  Top Layer w0.127: J58.21@108.778,8.856 108.778,9.511 109.022,9.754 v2(109.698,9.754)
  L3 w0.124: v2(109.698,9.754) 109.755,9.698 119.393,9.698 134.011,24.316 134.011,27 134.011,28.548 v3(133.759,28.8)
NetJ58_23: J58.23 MOD1.11 | length 46.7
  Top Layer w0.076: 134.084,26.75 MOD1.11@134.084,28
  Top Layer w0.127: J58.23@106.238,8.856 106.302,8.792 106.302,6.813 106.656,6.459 111.83,6.459 112.401,7.03 112.401,10.601 114.073,12.273 128.028,12.273 134.084,18.329 134.084,26.75
NetJ58_25: J58.25 MOD1.9 | length 42.3
  Top Layer w0.127: J58.25@103.699,8.857 103.556,9 103.556,9.342 104.483,9.342 v2(104.62,9.205)
  L3 w0.127: v2(104.62,9.205) 104.696,9.281 119.479,9.281 134.264,24.066 134.264,27 134.264,28.655 v3(134.409,28.8)
NetJ69_4: J69.4 MOD1.44 | length 47.9
  Top Layer w0.127: J69.4@81.868,30.983 83.908,30.983 v2(83.919,30.973)
  L3 w0.127: v2(83.919,30.973) 84.007,30.884 112.094,30.884 112.828,31.619 114.611,31.619 128.109,31.619 129.165,31.619 v4(129.359,31.425)
NetJ69_6: J69.6 MOD1.24 | length 51.4
  Top Layer w0.127: J69.6@81.868,28.443 82.993,28.443 v2(83.717,29.167)
  L3 w0.127: v2(83.717,29.167) 85.154,30.603 109.81,30.603 130.091,30.603 131.159,29.536 v3(131.159,28.8)
NetJ69_8: J69.8 MOD1.26 | length 52.3
  Top Layer w0.076: v3(130.787,29.4) 130.834,29.353 MOD1.26@130.834,28
  Top Layer w0.127: J69.8@81.868,25.903 82.97,25.903 83.789,26.722 v2(83.789,26.744)
  L3 w0.127: v2(83.789,26.744) 86.396,29.35 115.663,29.35 116.231,29.918 128.109,29.918 129.66,29.918 130.21,29.368 130.756,29.368 v3(130.787,29.4)
NetJ69_10: J69.10 MOD1.35 | length 57.6
  Top Layer w0.127: v2(123.475,28.393) 123.891,27.977 127.661,27.977 128.184,28.5 MOD1.35@128.559,28.5
  Top Layer w0.15: J69.10@81.868,23.363 83.047,23.363 v2(84.388,22.021)
  L3 w0.15: v2(84.388,22.021) 84.388,19.852 87.483,16.757 104.073,16.757 112.923,25.607 112.923,27.993 113.686,28.756 123.112,28.756 v2(123.475,28.393)
NetJ69_12: J69.12 MOD1.43 | length 58.5
  Top Layer w0.127: v2(113.645,27.274) 113.832,27.461 113.832,31.159 v2(113.817,31.174)
  Top Layer w0.15: J69.12@81.868,20.823 v2(83.773,20.823)
  L3 w0.127: 104.244,16.374 113.645,25.775 v2(113.645,27.274) ; v2(113.817,31.174) 114.013,31.369 128.109,31.369 128.29,31.369 v4(128.559,31.1)
  L3 w0.15: v2(83.773,20.823) 83.773,19.885 83.815,19.843 87.285,16.374 104.244,16.374
NetJ69_14: J69.14 MOD1.27 | length 59
  Top Layer w0.102: v3(130.433,29.773) 130.455,29.751 130.455,28.854 MOD1.27@130.509,28.8
  Top Layer w0.127: J69.14@81.868,18.283 83.773,18.283 v2(83.815,18.241) ; v2(114.433,30.19) 114.433,27.263 v2(114.438,27.258)
  L3 w0.127: v2(83.815,18.241) 84.587,18.241 86.766,16.062 104.459,16.062 114.438,26.04 v2(114.438,27.258) ; v2(114.433,30.19) 128.109,30.19 130.016,30.19 v3(130.433,29.773)
NetJ69_16: J69.16 MOD1.34 | length 52.1
  Top Layer w0.127: J69.16@81.868,15.743 81.868,15.917 v2(83.801,15.917)
  Top Layer w0.15: v2(126.177,27.39) 126.252,27.316 127.575,27.316 128.109,27.85 MOD1.34@128.559,27.85
  L3 w0.127: v2(83.801,15.917) 83.977,15.741 104.63,15.741 116.119,27.23 126.12,27.23 126.177,27.287 v2(126.177,27.39)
